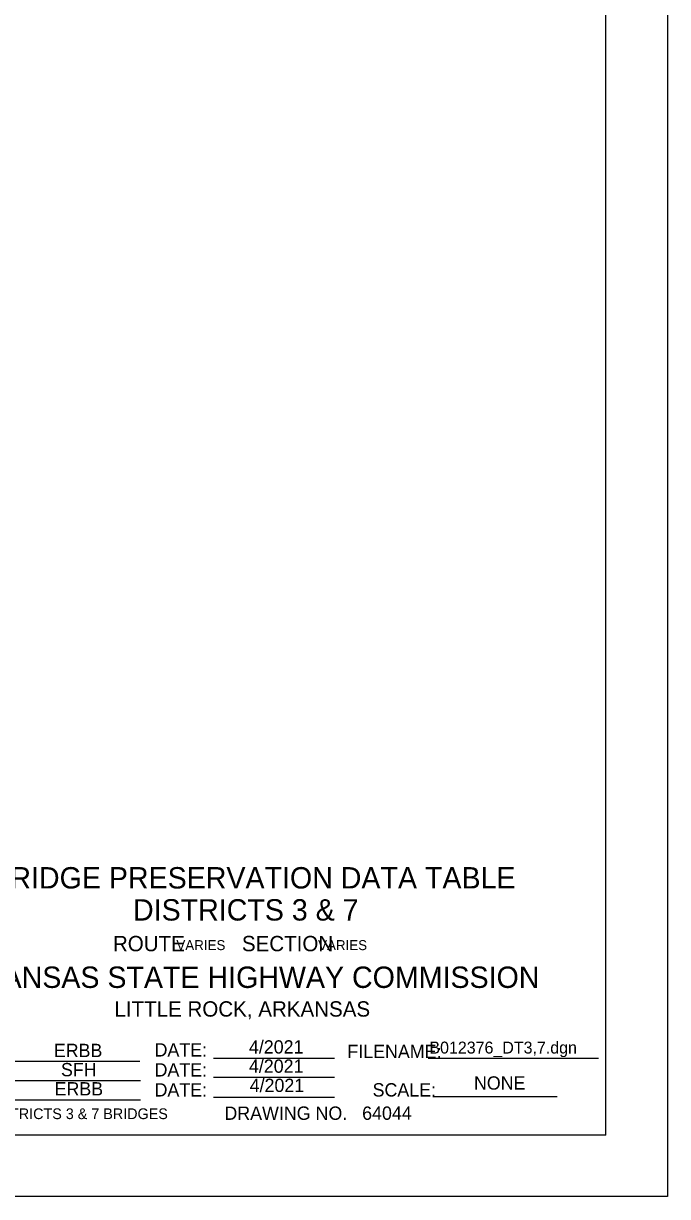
# Model space of a CAD drawing. Extents: x 16 to 1228740, y 11 to 152440.
# Drawn here: x 17.987 to 18.49, y 10.709 to 11.626 of the extents above; entities that cross this region are included whole.
import ezdxf

# ---------------------------------------------------------------- set-up
doc = ezdxf.new("R2010")
doc.units = 0
for name, color, linetype in [('B_Copy In', 7, 'Continuous'), ('B_Text', 7, 'Continuous'), ('B_Title Text', 7, 'Continuous'), ('R_Border', 7, 'Continuous')]:
    doc.layers.add(name, color=color, linetype=linetype)

msp = doc.modelspace()

# ---------------------------------------------------------------- linework, layer by layer
at = {"layer": 'B_Text'}
for p, q in [((18.13559, 10.81765), (18.23009, 10.81765)), ((18.30318, 10.81765), (18.43623, 10.81765)), ((17.97449, 10.81515), (18.07809, 10.81515)), ((17.97509, 10.80015), (18.07869, 10.80015)), ((18.13559, 10.80265), (18.23009, 10.80265)), ((18.13559, 10.80265), (18.23009, 10.80265)), ((17.97509, 10.78515), (18.07869, 10.78515)), ((18.13559, 10.78703), (18.23009, 10.78703)), ((18.30706, 10.78765), (18.40419, 10.78765))]:
    msp.add_line(p, q, dxfattribs=at)
at = {"layer": 'R_Border'}
for q in [(18.44221, 12.49475), (15.78327, 10.75755)]:
    msp.add_line((18.44221, 10.75755), q, dxfattribs=at)
msp.add_lwpolyline([(15.65694, 12.54282), (18.49027, 12.54282), (18.49027, 10.70949), (15.65694, 10.70949)], close=True, dxfattribs=at)

# ---------------------------------------------------------------- texts
at = {"layer": 'B_Copy In'}
for s, height, p in [('BRIDGE PRESERVATION DATA TABLE  ', 0.0167, (17.96204, 10.9502)), ('DISTRICTS 3 & 7', 0.0167, (18.07274, 10.92515)), ('ERBB', 0.0104, (18.01091, 10.81846)), ('4/2021', 0.0104, (18.16332, 10.82119)), ('B012376_DT3,7.dgn', 0.0093366, (18.30428, 10.82121)), ('4/2021', 0.0104, (18.16332, 10.80619)), ('SFH', 0.0104, (18.01647, 10.80346)), ('ERBB', 0.0104, (18.01151, 10.78846)), ('4/2021', 0.0104, (18.16392, 10.79119)), ('NONE', 0.0104, (18.3391, 10.79302)), ('64044', 0.010417, (18.25173, 10.76944)), ('DISTRICTS 3 & 7 BRIDGES', 0.0083776, (17.95802, 10.76999))]:
    msp.add_text(s, height=height, dxfattribs=at).set_placement(p)
at = {"layer": 'B_Text'}
for s, height, p in [('DATE:', 0.010417, (18.08959, 10.8189)), ('FILENAME:', 0.010417, (18.24018, 10.81765)), ('DATE:', 0.010417, (18.08959, 10.80328)), ('DATE:', 0.010417, (18.08959, 10.78765)), ('SCALE:', 0.010417, (18.25989, 10.78765)), ('DRAWING NO.', 0.0104166, (18.14412, 10.76942))]:
    msp.add_text(s, height=height, dxfattribs=at).set_placement(p)
at = {"layer": 'B_Title Text'}
for s, height, p in [('ROUTE          SECTION ', 0.012, (18.05705, 10.90115)), ('                VARIES                         VARIES', 0.0078, (18.06026, 10.90204)), ('ARKANSAS STATE HIGHWAY COMMISSION', 0.0167, (17.92492, 10.8725)), ('LITTLE ROCK, ARKANSAS', 0.012, (18.05823, 10.85007))]:
    msp.add_text(s, height=height, dxfattribs=at).set_placement(p)

doc.saveas('drawing.dxf')
